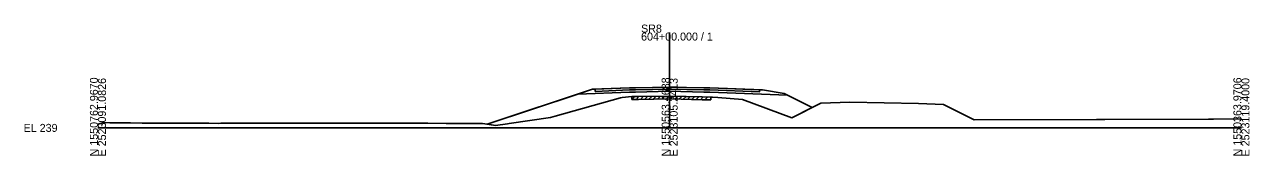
# Model space of a CAD drawing. Extents: x -26 to 2803, y -10 to 19537.
# Drawn here: x -25.7 to 402.8, y 11490.3 to 11536.2 of the extents above; entities that cross this region are included whole.
import ezdxf

# ---------------------------------------------------------------- set-up
doc = ezdxf.new("R2010")
doc.units = 0
for name, color, linetype in [('1', 7, 'Continuous'), ('Draft_XS_Grid', 7, 'Continuous'), ('Draft_XS_Text', 7, 'Continuous'), ('DTM_P_SUBGRADE_1', 7, 'Continuous'), ('DTM_X_GROUND', 7, 'Continuous'), ('SLOPE_STAKES_FILL', 7, 'Continuous'), ('XS_P_ASPHALT', 7, 'Continuous'), ('XS_P_SHOULDER', 7, 'Continuous')]:
    doc.layers.add(name, color=color, linetype=linetype)

msp = doc.modelspace()

# ---------------------------------------------------------------- linework, layer by layer
at = {"layer": '1'}
for p, q in [((200, 11500), (200, 11533.4)), ((0, 11500), (200, 11500)), ((200, 11500), (400, 11500))]:
    msp.add_line(p, q, dxfattribs=at)
at = {"layer": 'Draft_XS_Grid'}
for p, q in [((186.76, 11509.96), (187.77, 11510.98)), ((186.76, 11509.96), (186.76, 11510.96)), ((188.26, 11509.98), (189.27, 11510.99)), ((189.76, 11510), (190.77, 11511.01)), ((191.26, 11510.02), (192.27, 11511.03)), ((192.76, 11510.04), (193.77, 11511.05)), ((194.26, 11510.06), (195.27, 11511.07)), ((195.76, 11510.08), (196.77, 11511.09)), ((197.26, 11510.1), (198.27, 11511.11)), ((198.76, 11510.11), (199.77, 11511.13)), ((200.26, 11510.13), (201.24, 11511.11)), ((201.76, 11510.1), (202.73, 11511.07)), ((203.26, 11510.06), (204.23, 11511.04)), ((204.76, 11510.02), (205.73, 11511)), ((206.26, 11509.99), (207.23, 11510.96)), ((207.76, 11509.95), (208.73, 11510.93)), ((209.26, 11509.91), (210.23, 11510.89)), ((210.76, 11509.87), (211.73, 11510.85)), ((212.26, 11509.84), (213.23, 11510.81)), ((214.44, 11510.78), (214.44, 11509.78)), ((186.76, 11509.96), (189.07, 11509.99)), ((189.07, 11509.99), (200, 11510.13)), ((200, 11510.13), (200.32, 11510.13)), ((200.32, 11510.13), (211.42, 11509.86)), ((211.42, 11509.86), (214.44, 11509.78))]:
    msp.add_line(p, q, dxfattribs=at)
at = {"layer": 'Draft_XS_Text'}
for p, q in [((242.77, 11503.58), (252.86, 11508.62)), ((252.86, 11508.62), (263, 11509.02)), ((263, 11509.02), (275, 11508.78)), ((275, 11508.78), (287, 11508.54)), ((287, 11508.54), (295.81, 11508.19)), ((295.81, 11508.19), (306.53, 11502.84))]:
    msp.add_line(p, q, dxfattribs=at)
for points in [[(0, 11501.31), (2.03, 11501.84), (4.19, 11501.81), (4.62, 11501.81), (9.82, 11501.75), (11.35, 11501.74), (15.45, 11501.7), (18.09, 11501.69), (21.08, 11501.67), (24.81, 11501.66), (26.71, 11501.64), (31.54, 11501.63), (32.34, 11501.63), (36.51, 11501.63), (38.79, 11501.61), (42.22, 11501.59), (43.01, 11501.6), (43.75, 11501.6), (45.72, 11501.62), (47.05, 11501.63), (48.6, 11501.65), (50.13, 11501.66), (51.52, 11501.67), (53.15, 11501.69), (54.45, 11501.7), (56.15, 11501.71), (91.87, 11501.71), (95.47, 11501.69), (99.8, 11501.7), (104.2, 11501.67), (107.67, 11501.67), (112.97, 11501.63), (115.46, 11501.63), (121.79, 11501.57), (123.15, 11501.57), (130.8, 11501.48), (131.17, 11501.48), (134.53, 11501.5), (138.42, 11500.93), (139.05, 11500.84), (143.31, 11501.43), (143.8, 11501.5), (158.37, 11503.6), (159.98, 11504.05), (182.78, 11510.53), (183.44, 11510.6), (186.76, 11510.96), (189.07, 11510.99), (200, 11511.13), (200.32, 11511.13), (211.42, 11510.86), (214.44, 11510.78), (215.03, 11510.74), (216.82, 11510.6), (225.51, 11509.94), (242.77, 11503.58)], [(306.53, 11502.84), (349.34, 11502.97), (350.86, 11502.98), (351.21, 11502.98), (352.21, 11502.98), (388.44, 11503.09), (390.29, 11503.09), (400, 11503.12)]]:
    msp.add_lwpolyline(points, dxfattribs=at)
at = {"layer": 'DTM_P_SUBGRADE_1'}
for p, q in [((186, 11512.53), (167.87, 11511.8)), ((188, 11512.57), (186, 11512.53)), ((188, 11512.57), (200, 11512.81)), ((200, 11512.81), (212, 11512.57)), ((212, 11512.57), (214, 11512.53)), ((214, 11512.53), (241.2, 11511.44))]:
    msp.add_line(p, q, dxfattribs=at)
at = {"layer": 'DTM_X_GROUND'}
for p, q in [((172.99, 11513.51), (136.2, 11501.25)), ((186, 11514.03), (172.99, 11513.51)), ((188, 11514.07), (186, 11514.03)), ((188, 11514.07), (200, 11514.31)), ((200, 11514.31), (212, 11514.07)), ((212, 11514.07), (214, 11514.03)), ((214, 11514.03), (232.44, 11513.29)), ((232.44, 11513.29), (240.02, 11512.03)), ((240.02, 11512.03), (249.85, 11507.11))]:
    msp.add_line(p, q, dxfattribs=at)
at = {"layer": 'SLOPE_STAKES_FILL'}
for p, q in [((136.2, 11501.25), (172.99, 11513.51)), ((172.99, 11513.51), (186, 11514.03)), ((186, 11514.03), (188, 11514.07)), ((188, 11514.07), (200, 11514.31)), ((200, 11514.31), (212, 11514.07)), ((212, 11514.07), (214, 11514.03)), ((214, 11514.03), (232.44, 11513.29)), ((232.44, 11513.29), (240.02, 11512.03)), ((240.02, 11512.03), (249.85, 11507.11)), ((249.85, 11507.11), (252.86, 11508.62)), ((252.86, 11508.62), (263, 11509.02)), ((263, 11509.02), (275, 11508.78)), ((275, 11508.78), (287, 11508.54)), ((287, 11508.54), (295.81, 11508.19)), ((295.81, 11508.19), (306.53, 11502.84))]:
    msp.add_line(p, q, dxfattribs=at)
for points in [[(0, 11501.31), (2.03, 11501.84), (4.19, 11501.81), (4.62, 11501.81), (9.82, 11501.75), (11.35, 11501.74), (15.45, 11501.7), (18.09, 11501.69), (21.08, 11501.67), (24.81, 11501.66), (26.71, 11501.64), (31.54, 11501.63), (32.34, 11501.63), (36.51, 11501.63), (38.79, 11501.61), (42.22, 11501.59), (43.01, 11501.6), (43.75, 11501.6), (45.72, 11501.62), (47.05, 11501.63), (48.6, 11501.65), (50.13, 11501.66), (51.52, 11501.67), (53.15, 11501.69), (54.45, 11501.7), (56.15, 11501.71), (91.87, 11501.71), (95.47, 11501.69), (99.8, 11501.7), (104.2, 11501.67), (107.67, 11501.67), (112.97, 11501.63), (115.46, 11501.63), (121.79, 11501.57), (123.15, 11501.57), (130.8, 11501.48), (131.17, 11501.48), (134.53, 11501.5), (136.2, 11501.25)], [(306.53, 11502.84), (349.34, 11502.97), (350.86, 11502.98), (351.21, 11502.98), (352.21, 11502.98), (388.44, 11503.09), (390.29, 11503.09), (400, 11503.12)]]:
    msp.add_lwpolyline(points, dxfattribs=at)
at = {"layer": 'XS_P_ASPHALT'}
for p, q in [((173.99, 11512.8), (173.99, 11513.55)), ((186, 11513.28), (173.99, 11512.8)), ((188, 11513.32), (186, 11513.28)), ((188, 11513.32), (200, 11513.56)), ((200, 11513.56), (212, 11513.32)), ((212, 11513.32), (214, 11513.28)), ((214, 11513.28), (231.41, 11512.58)), ((231.41, 11512.58), (231.41, 11513.33))]:
    msp.add_line(p, q, dxfattribs=at)
at = {"layer": 'XS_P_SHOULDER'}
for points in [[(212, 11512.57), (214, 11512.53), (241.2, 11511.44), (249.85, 11507.11), (242.77, 11503.58), (225.51, 11509.94), (216.82, 11510.6), (215.03, 11510.74), (214.44, 11510.78), (211.42, 11510.86), (200.32, 11511.13), (200, 11511.13), (189.07, 11510.99), (186.76, 11510.96), (183.44, 11510.6), (182.78, 11510.53), (159.98, 11504.05), (158.37, 11503.6), (143.8, 11501.5), (143.31, 11501.43), (139.05, 11500.84), (138.42, 11500.93), (136.2, 11501.25), (167.87, 11511.8), (186, 11512.53), (188, 11512.57), (200, 11512.81)], [(212, 11512.57), (214, 11512.53), (241.2, 11511.44), (240.02, 11512.03), (232.44, 11513.29), (231.41, 11513.33), (231.41, 11512.58), (214, 11513.28), (212, 11513.32), (200, 11513.56), (188, 11513.32), (186, 11513.28), (173.99, 11512.8), (173.99, 11513.55), (172.99, 11513.51), (167.87, 11511.8), (186, 11512.53), (188, 11512.57), (200, 11512.81)], [(200, 11514.31), (212, 11514.07), (214, 11514.03), (231.41, 11513.33), (231.41, 11512.58), (214, 11513.28), (212, 11513.32), (200, 11513.56), (188, 11513.32), (186, 11513.28), (173.99, 11512.8), (173.99, 11513.55), (186, 11514.03), (188, 11514.07)]]:
    msp.add_lwpolyline(points, close=True, dxfattribs=at)

# ---------------------------------------------------------------- texts
at = {"layer": '1'}
for s, p in [('SR8', (190, 11533.4)), ('604+00.000 / 1', (190, 11530.6)), ('EL 239', (-26, 11498.6))]:
    msp.add_text(s, height=2.8, dxfattribs=at).set_placement(p)
for s, p in [('N 1550762.9670', (0, 11490)), ('E 2523091.0826', (2.8, 11490)), ('N 1550563.4688', (200, 11490)), ('E 2523105.2413', (202.8, 11490)), ('N 1550363.9706', (400, 11490)), ('E 2523119.4000', (402.8, 11490))]:
    msp.add_text(s, height=2.8, rotation=90, dxfattribs=at).set_placement(p)

doc.saveas('drawing.dxf')
